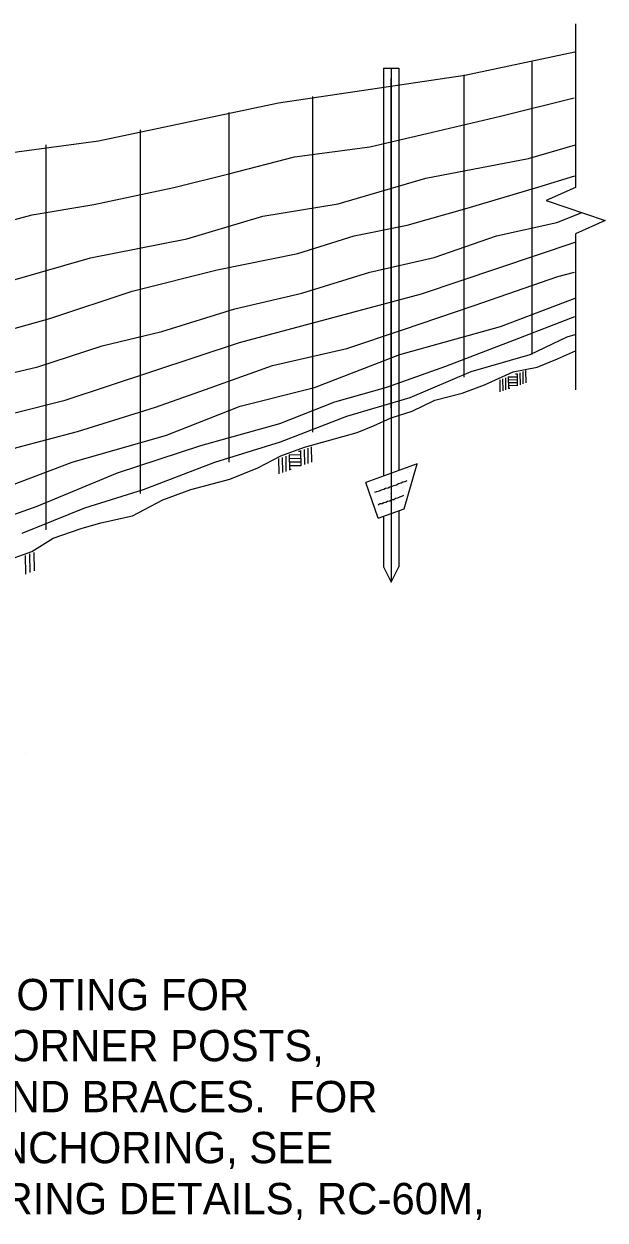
# Model space of a CAD drawing. Extents: x 13 to 918, y -903 to 879.
# Drawn here: x 612.7 to 670.6, y 517.8 to 637.1 of the extents above; entities that cross this region are included whole.
import ezdxf

# ---------------------------------------------------------------- set-up
doc = ezdxf.new("R2010")
doc.units = 0
for name, color, linetype in [('1', 7, 'Continuous'), ('2', 7, 'Continuous'), ('3', 7, 'Continuous')]:
    doc.layers.add(name, color=color, linetype=linetype)

msp = doc.modelspace()

# ---------------------------------------------------------------- linework, layer by layer
at = {"layer": '1'}
for p, q in [((662.4, 602.411), (662.421, 601.209)), ((662.6835, 602.51325), (662.70225, 601.311)), ((660.11875, 601.57975), (660.1375, 600.40075)), ((660.4, 601.682), (660.41675, 600.482)), ((660.67925, 601.782), (660.698, 600.582)), ((660.9585, 601.884), (660.97725, 600.684)), ((661.85625, 601.8715), (660.9605, 601.857)), ((661.8605, 601.58825), (660.96475, 601.57575)), ((661.86675, 601.309), (660.96675, 601.29225)), ((661.85225, 602.15075), (661.6855, 602.1485)), ((661.84375, 602.207), (661.8605, 601.007)), ((662.123, 602.309), (662.14175, 601.109)), ((661.86875, 601.02575), (660.973, 601.011)), ((661.10625, 600.732), (660.97725, 600.72975)), ((639.1355, 594.1235), (639.1605, 592.5965)), ((640.27925, 594.107), (639.1375, 594.08825)), ((640.273, 594.46325), (640.0605, 594.461)), ((640.2625, 594.534), (640.2855, 593.007)), ((640.61875, 594.66325), (640.64175, 593.136)), ((640.973, 594.79225), (640.998, 593.26525)), ((641.33125, 594.9235), (641.35425, 593.3945)), ((638.06675, 593.736), (638.08975, 592.236)), ((638.425, 593.86525), (638.448, 592.33825)), ((638.78125, 593.9945), (638.80425, 592.46725)), ((640.2855, 593.7485), (639.14375, 593.732)), ((640.29175, 593.39025), (639.148, 593.3715)), ((640.296, 593.032), (639.15425, 593.01325)), ((639.325, 592.657), (639.1605, 592.65475)), ((612.821, 584.0715), (612.848, 582.21725)), ((613.25, 584.22975), (613.28125, 582.3735)), ((613.6855, 584.38825), (613.71475, 582.532))]:
    msp.add_line(p, q, dxfattribs=at)
at = {"layer": '2'}
for p, q in [((667.66875, 637.08825), (667.66875, 620.78825)), ((648.51475, 632.66725), (650.0585, 632.66725)), ((648.51475, 632.66725), (648.51475, 592.00075)), ((649.2855, 632.66725), (649.2855, 581.407)), ((650.0585, 632.66725), (650.0585, 592.56325)), ((663.31675, 633.40475), (663.31675, 604.11525)), ((649.25425, 631.0465), (649.25425, 599.0715)), ((649.2855, 631.2945), (649.2855, 631.2945)), ((656.546, 632.00475), (656.546, 601.85275)), ((641.44175, 629.857), (641.44175, 596.386)), ((633.1085, 628.2465), (633.1085, 593.39225)), ((624.25425, 626.53825), (624.25425, 590.26525)), ((649.2855, 625.484), (649.2855, 625.484)), ((614.87925, 625.04225), (614.87925, 586.6215)), ((649.2855, 620.70075), (649.2855, 620.70075)), ((667.66875, 620.78825), (664.725, 619.48825)), ((664.725, 619.48825), (670.6125, 617.4695)), ((670.6125, 617.4695), (667.66875, 616.1695)), ((649.2855, 616.60075), (649.2855, 616.60075)), ((667.66875, 616.1695), (667.66875, 600.60475)), ((649.2855, 612.84225), (649.2855, 612.84225)), ((649.2855, 609.4235), (649.2855, 609.4235)), ((649.2855, 606.3465), (649.2855, 606.3465)), ((649.2855, 603.611), (649.2855, 603.611)), ((649.2855, 601.2215), (649.2855, 601.2215)), ((649.2855, 599.1715), (649.2855, 599.1715)), ((649.2855, 597.80475), (649.2855, 597.80475)), ((649.2855, 597.80475), (649.2855, 597.80475)), ((649.2855, 597.80475), (649.2855, 597.80475)), ((649.2855, 597.80475), (649.2855, 597.80475)), ((651.8875, 593.22775), (646.748, 591.359)), ((650.57725, 588.72975), (651.8875, 593.22775)), ((648.00625, 587.7985), (646.748, 591.359)), ((648.00625, 587.7985), (650.57725, 588.72975)), ((650.0585, 588.54225), (650.0585, 582.95075)), ((648.51475, 587.97975), (648.51475, 582.95075)), ((648.51475, 582.95075), (649.2855, 581.407)), ((649.2855, 581.407), (650.0585, 582.95075)), ((612.80425, 564.31525), (612.80425, 564.31525))]:
    msp.add_line(p, q, dxfattribs=at)
for points in [[(549.25425, 613.009), (550.79375, 613.284), (556.30625, 614.361), (561.59375, 615.407), (566.9835, 615.90475), (577.79375, 618.309), (592.946, 620.65275), (609.723, 624.02975), (620.13125, 625.42775), (638.046, 629.20275), (656.62725, 631.96725), (667.59375, 634.31725)], [(649.2855, 630.934), (649.275, 631.059), (649.296, 631.132), (649.27725, 631.22775), (649.298, 631.3215), (649.275, 631.42575), (649.29375, 631.52775), (649.2855, 631.65275)], [(549.25425, 604.15475), (549.25425, 604.15475), (554.923, 605.36525), (560.77725, 606.79025), (566.2375, 607.486), (572.9875, 609.3195), (578.95625, 610.2985), (584.7855, 611.83825), (591.50625, 612.87975), (600.2085, 615.30475), (606.30625, 616.136), (613.48975, 618.04225), (619.64175, 619.082), (627.6355, 620.78825), (633.23975, 622.182), (639.6375, 623.8195), (647.148, 624.836), (652.85, 626.15075), (660.1875, 627.8945), (667.548, 629.71725)], [(649.2855, 625.12575), (649.275, 625.25075), (649.296, 625.3215), (649.27725, 625.41725), (649.298, 625.511), (649.275, 625.61725), (649.29375, 625.7195), (649.2855, 625.8445)], [(549.25425, 596.86325), (549.44175, 596.91725), (554.173, 597.734), (558.87925, 599.2485), (564.45625, 600.67575), (569.57925, 601.60075), (575.4835, 603.30475), (581.72925, 604.3985), (588.5085, 606.407), (595.65, 607.71525), (603.15425, 609.8985), (611.1, 611.3965), (619.3335, 613.75275), (628.921, 615.6445), (636.48125, 617.9195), (643.996, 619.157), (652.75, 621.71725), (662.99175, 623.684), (667.66875, 625.0235)], [(549.25425, 590.61325), (549.29175, 590.634), (554.03125, 592.059), (560.30225, 593.407), (567.223, 595.5965), (573.60625, 596.8945), (579.2855, 598.67975), (584.86875, 600.14225), (590.65, 601.16325), (596.6835, 603.04225), (602.64375, 604.882), (608.44375, 605.82775), (615.248, 607.709), (623.475, 610.44225), (631.94175, 612.561), (639.9835, 614.19225), (645.59175, 615.94225), (650.87725, 617.02975), (656.86475, 618.6985), (663.90425, 620.8215), (667.5855, 621.95475)], [(549.325, 584.89225), (549.25425, 584.884), (551.346, 585.3715), (555.31875, 586.761), (559.3625, 587.534), (565.01675, 589.4715), (571.1875, 590.83825), (577.11875, 592.85275), (582.1605, 593.907), (587.55625, 595.7715), (591.75, 596.586), (597.273, 598.486), (602.90625, 599.70475), (609.23975, 601.7735), (614.0625, 602.90075), (620.49375, 604.97775), (626.425, 606.41525), (633.71875, 608.6735), (640.39175, 610.24025), (647.15425, 612.3485), (653.58125, 613.78825), (659.80625, 615.96525), (665.79175, 617.27975), (668.23975, 618.2445)], [(649.2855, 616.24025), (649.275, 616.36725), (649.296, 616.43825), (649.27725, 616.534), (649.298, 616.62575), (649.275, 616.732), (649.29375, 616.836), (649.2855, 616.959)], [(549.31475, 579.72575), (549.25425, 579.67575), (554.6105, 581.36525), (559.748, 583.00075), (565.04375, 584.10275), (575.51675, 587.711), (590.30625, 591.7485), (606.598, 596.9965), (616.78125, 599.559), (634.15625, 605.32975), (652.30625, 610.1715), (667.6355, 615.3195)], [(549.348, 574.9965), (549.25425, 574.98825), (554.85225, 576.7445), (560.548, 578.709), (565.921, 579.911), (572.46875, 582.36725), (578.321, 583.8985), (583.98125, 585.97575), (590.575, 587.63825), (599.0125, 590.86725), (605.00625, 592.26325), (611.97925, 594.832), (618.0085, 596.44025), (625.80625, 598.884), (631.2585, 600.7965), (637.473, 603.0235), (644.8585, 604.736), (650.4125, 606.57775), (657.55425, 608.9985), (665.8875, 611.911), (667.5585, 612.3235)], [(549.471, 570.882), (549.25425, 570.8215), (553.90225, 572.02575), (558.46675, 573.92775), (563.90625, 575.81325), (568.9335, 577.159), (574.67725, 579.3465), (580.8105, 580.95475), (587.398, 583.5195), (594.40625, 585.41525), (601.70425, 588.21325), (609.498, 590.36725), (617.50625, 593.3965), (626.90425, 596.07775), (634.25225, 598.9715), (641.6375, 600.82775), (650.15, 604.107), (660.19175, 606.91525), (667.63975, 609.736)], [(649.2855, 609.06525), (649.275, 609.19025), (649.296, 609.261), (649.27725, 609.359), (649.298, 609.45275), (649.275, 609.55475), (649.29375, 609.659), (649.2855, 609.782)], [(549.25425, 567.17575), (549.4355, 567.2485), (554.0605, 569.009), (560.21875, 570.80275), (566.96475, 573.484), (573.23975, 575.234), (578.775, 577.4215), (584.23975, 579.282), (589.9335, 580.71325), (595.81675, 583.0195), (601.62925, 585.282), (607.348, 586.64025), (613.998, 589.00475), (622.0105, 592.3195), (630.30225, 595.04025), (638.20625, 597.2445), (643.675, 599.38825), (648.86875, 600.85275), (654.723, 602.9465), (661.59175, 605.5695), (667.596, 607.8985)], [(612.49175, 586.31325), (618.76875, 588.81525), (624.58975, 590.65075), (631.71675, 593.39225), (638.26875, 595.40275), (644.873, 597.961), (651.19175, 599.82975), (657.25425, 602.4195), (663.1375, 604.134), (666.85, 605.89225), (667.63975, 606.11725)], [(610.5, 583.41725), (613.45425, 584.49225), (615.60225, 585.7965), (618.40225, 586.757), (620.33975, 587.35075), (623.50625, 588.0215), (626.51675, 589.634), (629.31675, 590.65075), (633.2105, 591.70475), (636.0125, 592.836), (638.275, 594.007), (640.65425, 594.8695), (643.0335, 595.561), (645.88975, 596.32775), (647.53975, 596.9985), (649.2855, 597.80475), (651.37725, 598.457), (653.6585, 599.5695), (656.3835, 600.259), (658.6085, 601.084), (661.46675, 602.38825), (663.84375, 602.8695), (665.87725, 603.6945), (667.66875, 604.4965)], [(649.2855, 603.25475), (649.275, 603.37975), (649.296, 603.45275), (649.27725, 603.5485), (649.298, 603.64225), (649.275, 603.7465), (649.29375, 603.85075), (649.2855, 603.9715)], [(649.2855, 598.811), (649.275, 598.93825), (649.296, 599.009), (649.27725, 599.107), (649.298, 599.20075), (649.275, 599.30475), (649.29375, 599.409), (649.2855, 599.52975)], [(647.66875, 590.382), (647.846, 590.4735), (648.1355, 590.5235), (648.31875, 590.634), (648.55625, 590.67575), (648.73975, 590.786), (648.98125, 590.8195), (649.1625, 590.94025), (649.3875, 590.97775), (649.56475, 591.0715), (649.821, 591.13825), (650.02725, 591.25475), (650.2855, 591.3195), (650.46875, 591.42775), (650.6835, 591.461), (650.873, 591.5485)], [(648, 589.1445), (648.15625, 589.25475), (648.40225, 589.2735), (648.5625, 589.37575), (648.76475, 589.39225), (648.9375, 589.4965), (649.173, 589.54025), (649.31475, 589.65075), (649.54375, 589.67575), (649.725, 589.7965), (649.96475, 589.82775), (650.1605, 589.94225), (650.346, 589.97975), (650.56875, 590.07775)]]:
    msp.add_lwpolyline(points, dxfattribs=at)

# ---------------------------------------------------------------- texts
at = {"layer": '3'}
for s, p in [('CONCRETE FOOTING FOR', (581.51675, 538.72775)), ('END POSTS, CORNER POSTS,', (581.51675, 533.64225)), ('PULL POSTS AND BRACES.  FOR', (581.51675, 528.557)), ('ALTERNATE ANCHORING, SEE', (581.51675, 523.4715)), ('DRIVE ANCHORING DETAILS, RC-60M,', (581.51675, 518.384))]:
    msp.add_text(s, height=3.1249995, dxfattribs=at).set_placement(p)

doc.saveas('drawing.dxf')
